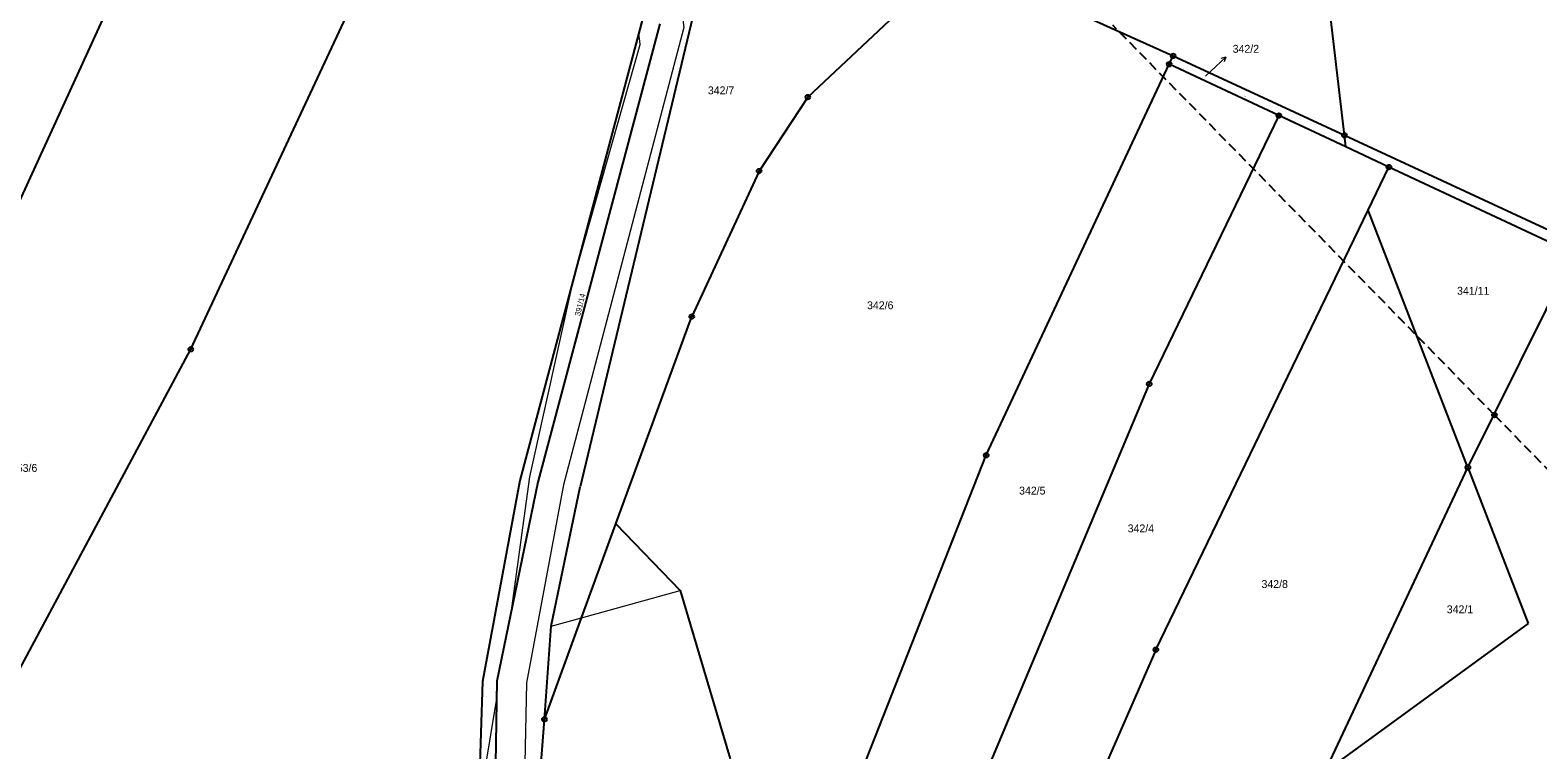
# Model space of a CAD drawing. Extents: x -504006 to -501322, y -1128098 to -1124665.
# Drawn here: x -502552.5 to -502227.9, y -1127162.4 to -1127007.5 of the extents above; entities that cross this region are included whole.
import ezdxf
from ezdxf.enums import TextEntityAlignment as Align

# ---------------------------------------------------------------- set-up
doc = ezdxf.new("R2010")
doc.units = 0
doc.header["$LTSCALE"] = 0.68
doc.linetypes.add('MEDIUM_DASHED', pattern=[4.5, 3, -1.5])
for name, color, linetype, lineweight in [('1', 7, 'Continuous', 25), ('13', 7, 'Continuous', 13), ('4', 7, 'Continuous', 13), ('6', 7, 'Continuous', 25), ('7', 7, 'Continuous', 13), ('8', 7, 'Continuous', 25)]:
    doc.layers.add(name, color=color, linetype=linetype, lineweight=lineweight)
doc.layers.add('2', color=7, linetype='Continuous')

msp = doc.modelspace()

# ---------------------------------------------------------------- linework, layer by layer
at = {"layer": '1'}
for p, q in [((-502569.42, -1127076.25), (-502506.22, -1126938.15)), ((-502517.95, -1127076.19), (-502463.83, -1126960.45)), ((-502269.52, -1127030.14), (-502276.45, -1126971.2)), ((-502338.27, -1126998.68), (-502306.39, -1127013.04)), ((-502420.31, -1127003.75), (-502447.1, -1127104.4)), ((-502416.95, -1127006.13), (-502443.22, -1127104.8)), ((-502409.84, -1127004.56), (-502434.09, -1127105.76)), ((-502367.57, -1127005.49), (-502385.06, -1127021.9)), ((-502307.25, -1127014.84), (-502306.39, -1127013.04)), ((-502306.39, -1127013.04), (-502269.52, -1127030.14)), ((-502346.64, -1127099), (-502307.25, -1127014.84)), ((-502283.61, -1127025.9), (-502307.25, -1127014.84)), ((-502385.06, -1127021.9), (-502395.57, -1127037.82)), ((-502283.61, -1127025.9), (-502311.55, -1127083.65)), ((-502269.22, -1127032.63), (-502283.61, -1127025.9)), ((-502269.22, -1127032.63), (-502269.52, -1127030.14)), ((-502269.52, -1127030.14), (-502131.13, -1127094.31)), ((-502259.92, -1127036.98), (-502269.22, -1127032.63)), ((-502395.57, -1127037.82), (-502410.07, -1127069.15)), ((-502264.38, -1127046.21), (-502259.92, -1127036.98)), ((-502220.12, -1127055.61), (-502259.92, -1127036.98)), ((-502310.1, -1127140.83), (-502264.38, -1127046.21)), ((-502242.92, -1127101.61), (-502264.38, -1127046.21)), ((-502242.92, -1127101.61), (-502220.12, -1127055.61)), ((-502426.39, -1127113.74), (-502410.07, -1127069.15)), ((-502603.6, -1127236.22), (-502517.95, -1127076.19)), ((-502311.55, -1127083.65), (-502357.89, -1127193.86)), ((-502374.12, -1127168.75), (-502346.64, -1127099)), ((-502273.66, -1127167.07), (-502242.92, -1127101.61)), ((-502242.92, -1127101.61), (-502229.92, -1127135.18)), ((-502447.1, -1127104.4), (-502455.08, -1127147.67)), ((-502443.22, -1127104.8), (-502452, -1127147.59)), ((-502440.31, -1127135.78), (-502434.09, -1127105.76)), ((-502433.78, -1127133.97), (-502426.39, -1127113.74)), ((-502426.39, -1127113.74), (-502412.56, -1127128.07)), ((-502412.56, -1127128.07), (-502401.75, -1127164.32)), ((-502441.78, -1127155.83), (-502433.78, -1127133.97)), ((-502441.78, -1127155.83), (-502440.31, -1127135.78)), ((-502229.92, -1127135.18), (-502273.66, -1127167.07)), ((-502310.1, -1127140.83), (-502341.17, -1127211.66)), ((-502455.08, -1127147.67), (-502455.97, -1127172.73)), ((-502452, -1127147.59), (-502452.47, -1127173.47)), ((-502442.95, -1127171.7), (-502441.78, -1127155.83))]:
    msp.add_line(p, q, dxfattribs=at)
at = {"layer": '13'}
msp.add_lwpolyline([(-502454.46, -1127166.14), (-502452.08, -1127151.78), (-502452, -1127147.59), (-502448.79, -1127131.92), (-502444.94, -1127103.66), (-502435.55, -1127061.26), (-502421.13, -1127010.62), (-502421.46, -1127008.07), (-502447.1, -1127104.4), (-502455.08, -1127147.67), (-502455.97, -1127172.73)], dxfattribs=at)
at = {"layer": '4'}
for p, q in [((-502433.78, -1127133.97), (-502412.56, -1127128.07)), ((-502440.31, -1127135.78), (-502433.78, -1127133.97))]:
    msp.add_line(p, q, dxfattribs=at)
msp.add_lwpolyline([(-502426.8, -1126972.66), (-502414.6, -1126984.27), (-502411.76, -1127006.91), (-502437.68, -1127105.38), (-502445.66, -1127147.93), (-502446.15, -1127172.16), (-502435.84, -1127204.7), (-502413.25, -1127241.73)], dxfattribs=at)
at = {"layer": '6', "linetype": 'MEDIUM_DASHED'}
for q in [(-502319.39, -1127006.45), (-502168.54, -1127160.44)]:
    msp.add_line((-502237.21, -1127090.33), q, dxfattribs=at)
at = {"layer": '6'}
for radius in [0.5, 0.4, 0.3, 0.2, 0.1]:
    msp.add_circle((-502237.2134, -1127090.3299), radius, dxfattribs=at)
at = {"layer": '7'}
msp.add_line((-502295.045, -1127013.293), (-502296.119, -1127013.61), dxfattribs=at)
msp.add_lwpolyline([(-502299.45, -1127017.38), (-502297.24, -1127015.34), (-502295.045, -1127013.293), (-502295.436, -1127014.343)], dxfattribs=at)
at = {"layer": '8'}
for centre, radius in [((-502306.39, -1127013.0399), 0.5), ((-502306.39, -1127013.0399), 0.0303), ((-502307.25, -1127014.8399), 0.5), ((-502307.25, -1127014.8399), 0.0303), ((-502385.06, -1127021.8999), 0.5), ((-502385.06, -1127021.8999), 0.0303), ((-502283.61, -1127025.8999), 0.5), ((-502283.61, -1127025.8999), 0.0303), ((-502269.52, -1127030.1399), 0.5), ((-502269.52, -1127030.1399), 0.0303), ((-502395.57, -1127037.8199), 0.5), ((-502395.57, -1127037.8199), 0.0303), ((-502259.92, -1127036.9799), 0.5), ((-502259.92, -1127036.9799), 0.0303), ((-502410.07, -1127069.1499), 0.5), ((-502410.07, -1127069.1499), 0.0303), ((-502517.95, -1127076.1899), 0.5), ((-502517.95, -1127076.1899), 0.0303), ((-502311.55, -1127083.6499), 0.5), ((-502311.55, -1127083.6499), 0.0303), ((-502346.64, -1127098.9999), 0.5), ((-502346.64, -1127098.9999), 0.0303), ((-502242.92, -1127101.6099), 0.5), ((-502242.92, -1127101.6099), 0.0303), ((-502310.1, -1127140.8299), 0.5), ((-502310.1, -1127140.8299), 0.0303), ((-502441.78, -1127155.8299), 0.5), ((-502441.78, -1127155.8299), 0.0303)]:
    msp.add_circle(centre, radius, dxfattribs=at)

# ---------------------------------------------------------------- texts
at = {"layer": '2'}
for s, p in [('342/2', (-502293.58, -1127012.375)), ('342/7', (-502406.59, -1127021.315)), ('342/6', (-502372.31, -1127067.565)), ('342/5', (-502339.57, -1127107.445)), ('342/4', (-502316.19, -1127115.575))]:
    msp.add_text(s, height=1.7, dxfattribs=at).set_placement(p)
at = {"layer": '2', "width": 1.05}
msp.add_text('342/2', height=0.2, rotation=335, dxfattribs=at).set_placement((-502291.0588, -1127021.8052), align=Align.CENTER)
at = {"layer": '2'}
msp.add_text('391/14', height=1.2, rotation=76, dxfattribs=at).set_placement((-502434.118, -1127069.102))
for s, p in [('341/11', (-502241.78, -1127064.445)), ('353/6', (-502553.82, -1127102.565)), ('342/8', (-502284.53, -1127127.555)), ('342/1', (-502244.63, -1127132.995))]:
    msp.add_text(s, height=1.7, dxfattribs=at).set_placement(p, align=Align.CENTER)

doc.saveas('drawing.dxf')
